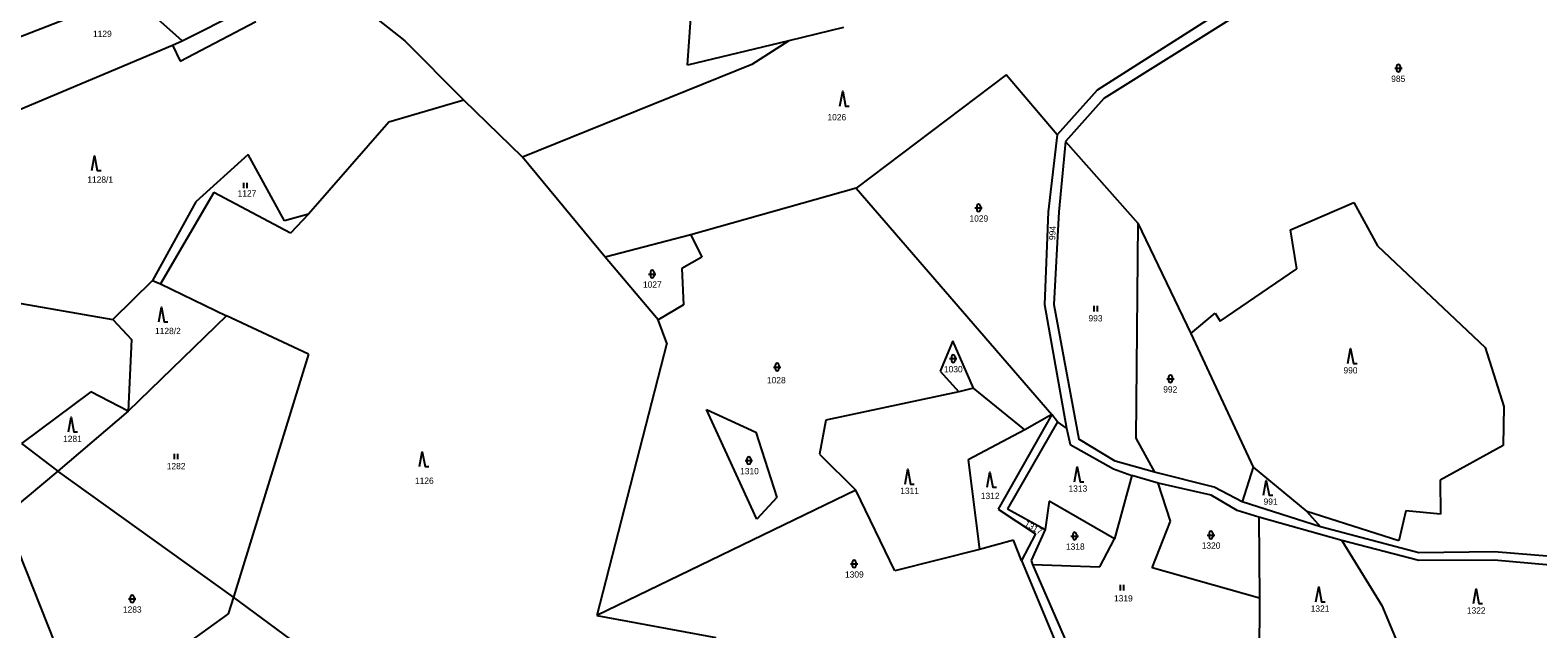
# Model space of a CAD drawing. Extents: x -670359 to -668019, y -978807 to -976674.
# Drawn here: x -669982.9 to -669575.5, y -977942.9 to -977781.2 of the extents above; entities that cross this region are included whole.
import ezdxf

# ---------------------------------------------------------------- set-up
doc = ezdxf.new("R2010")
doc.units = 0
for name, color, linetype in [('Hranice parcel', 7, 'Continuous'), ('Parcelní čísla', 7, 'Continuous'), ('Značky kultur', 7, 'Continuous')]:
    doc.layers.add(name, color=color, linetype=linetype)

msp = doc.modelspace()

# ---------------------------------------------------------------- linework, layer by layer
at = {"layer": 'Hranice parcel'}
for points in [[(-669805.3, -977790.58), (-669802.62, -977753.64)], [(-669904.6, -977765.84), (-669881.63, -977784.08)], [(-669941.84, -977784.04), (-669958.16, -977769.43)], [(-669966.28, -977775.47), (-669994.9, -977786.6)], [(-669941.84, -977784.04), (-669925.89, -977776.03)], [(-669657.21, -977773.63), (-669694.58, -977797.35)], [(-669655.51, -977776.26), (-669692.73, -977799.65)], [(-669942.37, -977789.56), (-669921.96, -977778.81)], [(-669763.13, -977780.42), (-669777.91, -977784.02)], [(-669987.66, -977803.37), (-669944.4, -977785.17)], [(-669944.4, -977785.17), (-669941.84, -977784.04)], [(-669944.4, -977785.17), (-669942.37, -977789.56)], [(-669865.71, -977800.05), (-669881.63, -977784.08)], [(-669777.91, -977784.02), (-669805.3, -977790.58)], [(-669777.91, -977784.02), (-669787.87, -977790.47)], [(-669787.87, -977790.47), (-669849.87, -977815.46)], [(-669719.16, -977793.18), (-669759.7, -977823.87)], [(-669705.39, -977809.4), (-669719.16, -977793.18)], [(-669694.58, -977797.35), (-669705.39, -977809.4)], [(-669865.71, -977800.05), (-669885.99, -977806)], [(-669849.87, -977815.46), (-669865.71, -977800.05)], [(-669692.73, -977799.65), (-669703.15, -977811.22)], [(-669885.99, -977806), (-669907.68, -977830.82)], [(-669705.39, -977809.4), (-669707.84, -977830.27)], [(-669703.15, -977811.22), (-669704.96, -977830.25)], [(-669703.15, -977811.22), (-669683.59, -977833.32)], [(-669924.01, -977814.78), (-669938.09, -977827.49)], [(-669914.15, -977832.7), (-669924.01, -977814.78)], [(-669827.49, -977842.49), (-669849.87, -977815.46)], [(-669933.23, -977824.98), (-669947.65, -977849.68)], [(-669912.54, -977835.97), (-669933.23, -977824.98)], [(-669759.7, -977823.87), (-669804.33, -977836.44)], [(-669759.7, -977823.87), (-669706.83, -977885.01)], [(-669938.09, -977827.49), (-669949.81, -977848.74)], [(-669642.32, -977835.07), (-669625.25, -977827.7)], [(-669625.25, -977827.7), (-669618.86, -977839.41)], [(-669907.68, -977830.82), (-669914.15, -977832.7)], [(-669907.68, -977830.82), (-669912.54, -977835.97)], [(-669707.84, -977830.27), (-669708.83, -977855.29)], [(-669704.96, -977830.25), (-669706.27, -977855.27)], [(-669683.59, -977833.32), (-669684.16, -977891.34)], [(-669683.59, -977833.32), (-669669.28, -977863.13)], [(-669804.33, -977836.44), (-669827.49, -977842.49)], [(-669804.33, -977836.44), (-669801.42, -977842.5)], [(-669640.58, -977845.61), (-669642.32, -977835.07)], [(-669618.86, -977839.41), (-669589.77, -977866.89)], [(-669813.16, -977859.43), (-669827.49, -977842.49)], [(-669801.42, -977842.5), (-669806.84, -977845.57)], [(-669806.84, -977845.57), (-669806.39, -977855.39)], [(-669661.3, -977859.8), (-669640.58, -977845.61)], [(-670018.5, -977849.23), (-669960.55, -977859.27)], [(-669949.81, -977848.74), (-669960.55, -977859.27)], [(-669949.81, -977848.74), (-669947.65, -977849.68)], [(-669947.65, -977849.68), (-669929.85, -977858.29)], [(-669929.85, -977858.29), (-669956.42, -977884.1)], [(-669907.72, -977868.7), (-669929.85, -977858.29)], [(-669806.39, -977855.39), (-669813.16, -977859.43)], [(-669708.83, -977855.29), (-669702.89, -977888.66)], [(-669706.27, -977855.27), (-669699.51, -977891.67)], [(-669669.28, -977863.13), (-669662.67, -977857.57)], [(-669662.67, -977857.57), (-669661.3, -977859.8)], [(-669960.55, -977859.27), (-669955.56, -977864.75)], [(-669810.89, -977865.73), (-669813.16, -977859.43)], [(-669955.56, -977864.75), (-669956.42, -977884.1)], [(-669810.89, -977865.73), (-669829.77, -977939.28)], [(-669733.56, -977865.03), (-669736.96, -977873.28)], [(-669727.98, -977877.86), (-669733.56, -977865.03)], [(-669669.28, -977863.13), (-669652.45, -977899.23)], [(-669907.72, -977868.7), (-669928, -977934.27)], [(-669589.77, -977866.89), (-669584.64, -977882.84)], [(-669736.96, -977873.28), (-669731.97, -977878.84)], [(-669966.52, -977878.8), (-669985.24, -977892.82)], [(-669956.42, -977884.1), (-669966.52, -977878.8)], [(-669731.97, -977878.84), (-669767.92, -977886.49)], [(-669727.98, -977877.86), (-669731.97, -977878.84)], [(-669714.16, -977889.12), (-669727.98, -977877.86)], [(-669584.64, -977882.84), (-669584.83, -977893.31)], [(-669956.42, -977884.1), (-669975.44, -977900.27)], [(-669800.16, -977883.64), (-669786.85, -977889.72)], [(-669786.56, -977913.21), (-669800.16, -977883.64)], [(-669767.92, -977886.49), (-669769.63, -977895.69)], [(-669706.83, -977885.01), (-669721.32, -977910.58)], [(-669705.3, -977886.91), (-669718.76, -977910.49)], [(-669706.83, -977885.01), (-669714.16, -977889.12)], [(-669705.3, -977886.91), (-669706.83, -977885.01)], [(-669702.89, -977888.66), (-669705.3, -977886.91)], [(-669786.85, -977889.72), (-669781.16, -977907.42)], [(-669714.16, -977889.12), (-669729.47, -977897.21)], [(-669702.89, -977888.66), (-669701.9, -977893.05)], [(-669985.24, -977892.82), (-669975.44, -977900.27)], [(-669701.9, -977893.05), (-669690.19, -977899.61)], [(-669689.72, -977897.61), (-669699.51, -977891.67)], [(-669684.16, -977891.34), (-669679.07, -977900.58)], [(-669584.83, -977893.31), (-669601.89, -977902.68)], [(-669769.63, -977895.69), (-669759.82, -977905.38)], [(-669729.47, -977897.21), (-669726.38, -977921.4)], [(-669679.07, -977900.58), (-669689.72, -977897.61)], [(-669652.45, -977899.23), (-669655.36, -977908.59)], [(-669652.45, -977899.23), (-669637.91, -977911.13)], [(-669975.44, -977900.27), (-669995.43, -977916.93)], [(-669928, -977934.27), (-669975.44, -977900.27)], [(-669690.19, -977899.61), (-669685.23, -977901.42)], [(-669685.23, -977901.42), (-669689.85, -977918.55)], [(-669678.1, -977903.53), (-669685.23, -977901.42)], [(-669662.98, -977904.56), (-669679.07, -977900.58)], [(-669601.89, -977902.68), (-669601.76, -977911.87)], [(-669759.82, -977905.38), (-669829.77, -977939.28)], [(-669781.16, -977907.42), (-669786.56, -977913.21)], [(-669749.22, -977927.21), (-669759.82, -977905.38)], [(-669663.76, -977906.8), (-669678.1, -977903.53)], [(-669674.76, -977913.82), (-669678.1, -977903.53)], [(-669656.78, -977910.92), (-669663.76, -977906.8)], [(-669655.36, -977908.59), (-669662.98, -977904.56)], [(-669721.32, -977910.58), (-669711.21, -977917.24)], [(-669718.76, -977910.49), (-669708.58, -977916.02)], [(-669707.58, -977908.34), (-669708.58, -977916.02)], [(-669689.85, -977918.55), (-669707.58, -977908.34)], [(-669650.86, -977912.72), (-669656.78, -977910.92)], [(-669634.21, -977915.34), (-669655.36, -977908.59)], [(-669637.91, -977911.13), (-669634.21, -977915.34)], [(-669613.08, -977919.05), (-669637.91, -977911.13)], [(-669611.2, -977910.97), (-669613.08, -977919.05)], [(-669601.76, -977911.87), (-669611.2, -977910.97)], [(-669679.73, -977926.4), (-669674.76, -977913.82)], [(-669628.43, -977918.98), (-669650.86, -977912.72)], [(-669650.86, -977912.72), (-669650.74, -977934.54)], [(-669607.62, -977922.29), (-669634.21, -977915.34)], [(-669717.2, -977918.95), (-669726.38, -977921.4)], [(-669715.01, -977924.37), (-669717.2, -977918.95)], [(-669711.21, -977917.24), (-669715.01, -977924.37)], [(-669708.58, -977916.02), (-669712.45, -977924.36)], [(-669693.81, -977926.08), (-669689.85, -977918.55)], [(-669607.61, -977924.37), (-669628.43, -977918.98)], [(-669628.43, -977918.98), (-669617.62, -977936.58)], [(-669986.12, -977921.83), (-669974.21, -977951.73)], [(-669726.38, -977921.4), (-669749.22, -977927.21)], [(-669587.31, -977922.09), (-669607.62, -977922.29)], [(-669566.4, -977923.76), (-669587.31, -977922.09)], [(-669715.01, -977924.37), (-669705.6, -977947.07)], [(-669712.45, -977924.36), (-669712.05, -977925.47)], [(-669712.05, -977925.47), (-669701.36, -977950.02)], [(-669712.05, -977925.47), (-669693.81, -977926.08)], [(-669650.74, -977934.54), (-669679.73, -977926.4)], [(-669587.3, -977924.33), (-669607.61, -977924.37)], [(-669567.14, -977926.07), (-669587.3, -977924.33)], [(-669928, -977934.27), (-669929.41, -977938.84)], [(-669912.5, -977945.77), (-669928, -977934.27)], [(-669650.74, -977934.54), (-669650.81, -977950.68)], [(-669929.41, -977938.84), (-669967.89, -977966.56)], [(-669829.77, -977939.28), (-669797.59, -977945.16)], [(-669617.62, -977936.58), (-669611.71, -977950.77)]]:
    msp.add_lwpolyline(points, dxfattribs=at)
at = {"layer": 'Značky kultur'}
for p, q in [((-669614.18, -977791.42), (-669612.18, -977791.42)), ((-669613.68, -977790.92), (-669613.68, -977791.92)), ((-669612.68, -977790.92), (-669612.68, -977791.92)), ((-669925.29, -977822.36), (-669925.29, -977823.86)), ((-669924.29, -977823.86), (-669924.29, -977822.36)), ((-669727.61, -977829.17), (-669725.61, -977829.17)), ((-669727.11, -977828.67), (-669727.11, -977829.67)), ((-669726.11, -977828.67), (-669726.11, -977829.67)), ((-669815.8, -977847.02), (-669813.8, -977847.02)), ((-669815.3, -977846.52), (-669815.3, -977847.52)), ((-669814.3, -977846.52), (-669814.3, -977847.52)), ((-669695.48, -977855.63), (-669695.48, -977857.13)), ((-669694.48, -977857.13), (-669694.48, -977855.63)), ((-669734.48, -977869.88), (-669732.48, -977869.88)), ((-669733.98, -977869.38), (-669733.98, -977870.38)), ((-669732.98, -977869.38), (-669732.98, -977870.38)), ((-669782.08, -977872.14), (-669780.08, -977872.14)), ((-669781.58, -977871.64), (-669781.58, -977872.64)), ((-669780.58, -977871.64), (-669780.58, -977872.64)), ((-669675.29, -977874.83), (-669675.29, -977875.83)), ((-669674.29, -977874.83), (-669674.29, -977875.83)), ((-669675.79, -977875.33), (-669673.79, -977875.33)), ((-669943.99, -977895.55), (-669943.99, -977897.05)), ((-669942.99, -977897.05), (-669942.99, -977895.55)), ((-669789.7, -977897.4), (-669787.7, -977897.4)), ((-669789.2, -977896.9), (-669789.2, -977897.9)), ((-669788.2, -977896.9), (-669788.2, -977897.9)), ((-669701.65, -977917.79), (-669699.65, -977917.79)), ((-669701.15, -977917.29), (-669701.15, -977918.29)), ((-669700.15, -977917.29), (-669700.15, -977918.29)), ((-669664.82, -977917.52), (-669662.82, -977917.52)), ((-669664.32, -977917.02), (-669664.32, -977918.02)), ((-669663.32, -977917.02), (-669663.32, -977918.02)), ((-669761.25, -977925.32), (-669759.25, -977925.32)), ((-669760.75, -977924.82), (-669760.75, -977925.82)), ((-669759.75, -977924.82), (-669759.75, -977925.82)), ((-669688.35, -977930.97), (-669688.35, -977932.47)), ((-669687.35, -977932.47), (-669687.35, -977930.97)), ((-669956.34, -977934.79), (-669954.34, -977934.79)), ((-669955.84, -977934.29), (-669955.84, -977935.29)), ((-669954.84, -977934.29), (-669954.84, -977935.29))]:
    msp.add_line(p, q, dxfattribs=at)
for points in [[(-669764.09, -977801.64), (-669763.34, -977797.64), (-669762.59, -977801.64), (-669761.59, -977801.64)], [(-669966.26, -977819.07), (-669965.51, -977815.07), (-669964.76, -977819.07), (-669963.76, -977819.07)], [(-669948.16, -977859.97), (-669947.41, -977855.97), (-669946.66, -977859.97), (-669945.66, -977859.97)], [(-669626.84, -977871.18), (-669626.09, -977867.18), (-669625.34, -977871.18), (-669624.34, -977871.18)], [(-669972.58, -977889.69), (-669971.83, -977885.69), (-669971.08, -977889.69), (-669970.08, -977889.69)], [(-669877.68, -977899.02), (-669876.93, -977895.02), (-669876.18, -977899.02), (-669875.18, -977899.02)], [(-669700.7, -977903.13), (-669699.95, -977899.13), (-669699.2, -977903.13), (-669698.2, -977903.13)], [(-669746.49, -977903.74), (-669745.74, -977899.74), (-669744.99, -977903.74), (-669743.99, -977903.74)], [(-669724.3, -977904.58), (-669723.55, -977900.58), (-669722.8, -977904.58), (-669721.8, -977904.58)], [(-669649.63, -977906.75), (-669648.88, -977902.75), (-669648.13, -977906.75), (-669647.13, -977906.75)], [(-669635.44, -977935.55), (-669634.69, -977931.55), (-669633.94, -977935.55), (-669632.94, -977935.55)], [(-669592.92, -977936.05), (-669592.17, -977932.05), (-669591.42, -977936.05), (-669590.42, -977936.05)]]:
    msp.add_lwpolyline(points, dxfattribs=at)
for centre, start, end in [((-669613.18, -977790.92), 0, 180), ((-669613.18, -977791.92), 180, 0), ((-669726.61, -977828.67), 0, 180), ((-669726.61, -977829.67), 180, 0), ((-669814.8, -977846.52), 0, 180), ((-669814.8, -977847.52), 180, 0), ((-669733.48, -977869.38), 0, 180), ((-669733.48, -977870.38), 180, 0), ((-669781.08, -977871.64), 0, 180), ((-669781.08, -977872.64), 180, 0), ((-669674.79, -977874.83), 0, 180), ((-669674.79, -977875.83), 180, 0), ((-669788.7, -977896.9), 0, 180), ((-669788.7, -977897.9), 180, 0), ((-669700.65, -977917.29), 0, 180), ((-669700.65, -977918.29), 180, 0), ((-669663.82, -977917.02), 0, 180), ((-669663.82, -977918.02), 180, 0), ((-669760.25, -977924.82), 0, 180), ((-669760.25, -977925.82), 180, 0), ((-669955.34, -977934.29), 0, 180), ((-669955.34, -977935.29), 180, 0)]:
    msp.add_arc(centre, 0.5, start, end, dxfattribs=at)

# ---------------------------------------------------------------- texts
at = {"layer": 'Parcelní čísla'}
for s, p in [('1129', (-669965.92, -977783)), ('985', (-669615.11, -977795.12)), ('1026', (-669767.45, -977805.51)), ('1128/1', (-669967.46, -977822.38)), ('1127', (-669926.84, -977826.09)), ('1029', (-669729.07, -977832.87)), ('1027', (-669817.3, -977850.72)), ('993', (-669696.91, -977859.83)), ('1128/2', (-669949.16, -977863.26)), ('1028', (-669783.8, -977876.53)), ('1030', (-669735.98, -977873.58)), ('990', (-669628.02, -977873.88)), ('992', (-669676.72, -977879.03)), ('1281', (-669974.01, -977892.39)), ('1282', (-669945.99, -977899.75)), ('1126', (-669878.92, -977903.7)), ('1310', (-669791.06, -977901.1)), ('1311', (-669747.78, -977906.44)), ('1312', (-669726.01, -977907.8)), ('1313', (-669702.31, -977905.83)), ('991', (-669649.6, -977909.35)), ('1320', (-669666.32, -977921.22)), ('1318', (-669703.01, -977921.49)), ('1309', (-669762.71, -977929.02)), ('1319', (-669690.02, -977935.47)), ('1283', (-669957.84, -977938.49)), ('1321', (-669636.87, -977938.25)), ('1322', (-669594.67, -977938.75))]:
    msp.add_text(s, height=1.7, dxfattribs=at).set_placement(p)
for s, rotation, p in [('994', 88.2432, (-669705.89, -977837.87)), ('1317', 330.2551, (-669714.4, -977914.98))]:
    msp.add_text(s, height=1.7, rotation=rotation, dxfattribs=at).set_placement(p)

doc.saveas('drawing.dxf')
